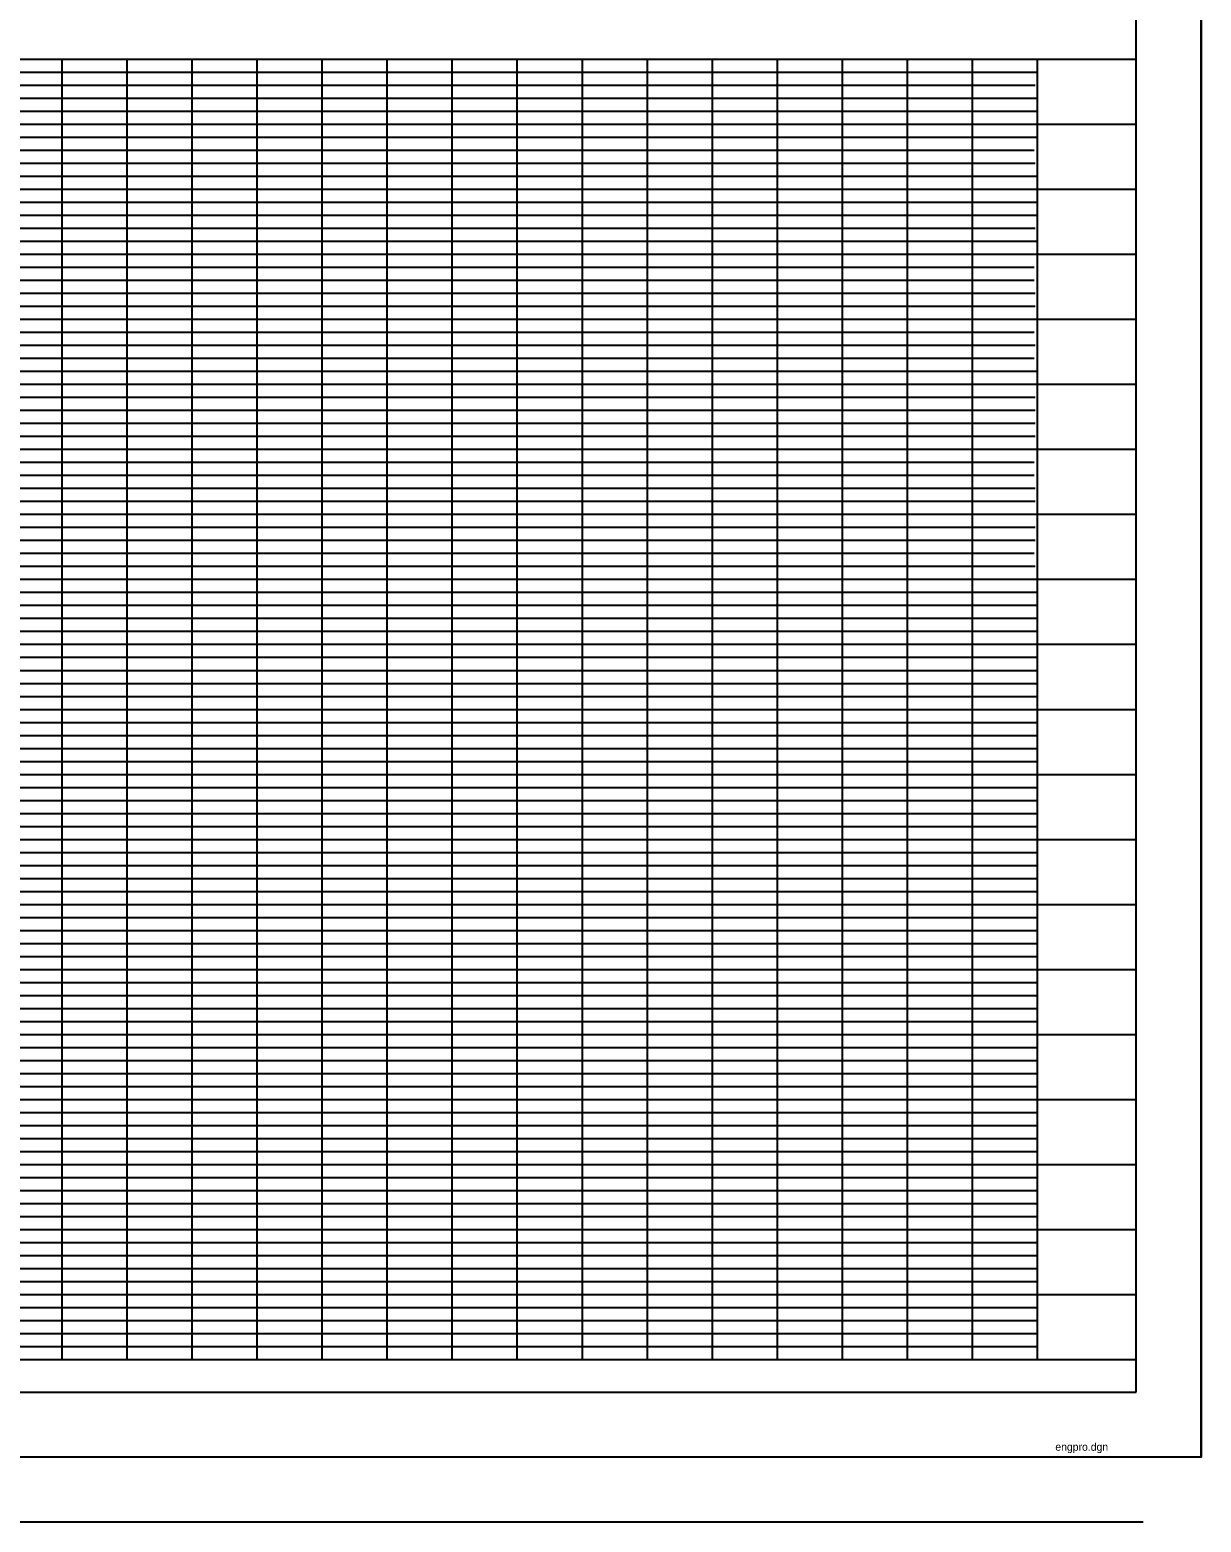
# Model space of a CAD drawing. Extents: x -184 to 1613, y -563 to 2888.
# Drawn here: x 1163 to 1613, y 588 to 1161 of the extents above; entities that cross this region are included whole.
import ezdxf

# ---------------------------------------------------------------- set-up
doc = ezdxf.new("R2010")
doc.units = 0
for name, color, linetype in [('RD_SHT_Bndy', 7, 'Continuous'), ('RD_SHT_IplotShp', 7, 'Continuous'), ('RD_SHT_MjGrid', 7, 'Continuous'), ('RD_SHT_MnGrid', 7, 'Continuous'), ('RD_SHT_Snap', 7, 'Continuous'), ('RD_SHT_SubGrid', 7, 'Continuous'), ('RD_SHT_TX', 7, 'Continuous')]:
    doc.layers.add(name, color=color, linetype=linetype)

msp = doc.modelspace()

# ---------------------------------------------------------------- linework, layer by layer
at = {"layer": 'RD_SHT_Bndy'}
for p, q in [((1588, 637.5), (1588, 1687.5)), ((-87, 1150), (1588, 1150)), ((1550, 1150), (1550, 650)), ((-87, 650), (1588, 650)), ((-87, 637.5), (1588, 637.5)), ((1590.65, 612.5), (-169.35, 612.5)), ((1590.65, 587.5), (-169.35, 587.5)), ((1590.65, 587.5), (-169.35, 587.5))]:
    msp.add_line(p, q, dxfattribs=at)
at = {"layer": 'RD_SHT_IplotShp'}
msp.add_lwpolyline([(-182.9, 1712.5), (1613, 1712.5), (1613, 612.5), (-182.9, 612.5)], close=True, dxfattribs=at)
at = {"layer": 'RD_SHT_MjGrid'}
for p, q in [((1200, 1150), (1200, 650)), ((1250, 1150), (1250, 650)), ((1300, 1150), (1300, 650)), ((1350, 1150), (1350, 650)), ((1400, 1150), (1400, 650)), ((1450, 1150), (1450, 650)), ((1500, 1150), (1500, 650)), ((-87, 1100), (1588, 1100)), ((-87, 1050), (1588, 1050)), ((-87, 1000), (1588, 1000)), ((-87, 950), (1588, 950)), ((-87, 900), (1588, 900)), ((-87, 850), (1588, 850)), ((-87, 800), (1588, 800)), ((-87, 750), (1588, 750)), ((-87, 700), (1588, 700))]:
    msp.add_line(p, q, dxfattribs=at)
at = {"layer": 'RD_SHT_MnGrid'}
for p, q in [((1175, 1150), (1175, 650)), ((1225, 1150), (1225, 650)), ((1275, 1150), (1275, 650)), ((1325, 1150), (1325, 650)), ((1375, 1150), (1375, 650)), ((1425, 1150), (1425, 650)), ((1475, 1150), (1475, 650)), ((1525, 1150), (1525, 650)), ((-87, 1125), (1588, 1125)), ((-87, 1075), (1588, 1075)), ((-87, 1025), (1588, 1025)), ((-87, 975), (1588, 975)), ((-87, 925), (1588, 925)), ((-87, 875), (1588, 875)), ((-87, 825), (1588, 825)), ((-87, 775), (1588, 775)), ((-87, 725), (1588, 725)), ((-87, 675), (1588, 675))]:
    msp.add_line(p, q, dxfattribs=at)
at = {"layer": 'RD_SHT_Snap'}
msp.add_line((1613, 612.5), (1613, 1712.5), dxfattribs=at)
at = {"layer": 'RD_SHT_SubGrid'}
for p, q in [((-49.95, 1145), (1549.8, 1145)), ((-49.95, 1140), (1549.25, 1140)), ((-49.95, 1135), (1549.8, 1135)), ((-49.9, 1130), (1549.8, 1130)), ((-49.95, 1120), (1549.8, 1120)), ((-49.95, 1115), (1548.75, 1115)), ((-49.95, 1110), (1549.25, 1110)), ((-49.95, 1105), (1549.8, 1105)), ((-49.95, 1095), (1549.8, 1095)), ((-49.95, 1090), (1549.8, 1090)), ((-49.95, 1085), (1549.25, 1085)), ((-49.95, 1080), (1549.8, 1080)), ((-49.95, 1070), (1548.75, 1070)), ((-49.95, 1065), (1548.75, 1065)), ((-49.95, 1060), (1549.25, 1060)), ((-49.95, 1055), (1549.25, 1055)), ((-49.95, 1045), (1548.75, 1045)), ((-49.95, 1040), (1549.25, 1040)), ((-49.95, 1035), (1548.75, 1035)), ((-49.9, 1030), (1549.8, 1030)), ((-49.95, 1020), (1549.25, 1020)), ((-49.95, 1015), (1549.25, 1015)), ((-49.95, 1010), (1549.25, 1010)), ((-49.95, 1005), (1549.25, 1005)), ((-49.85, 995), (1548.75, 995)), ((-49.85, 990), (1548.75, 990)), ((-49.9, 985), (1549.25, 985)), ((-49.9, 980), (1549.25, 980)), ((-49.95, 970), (1549.25, 970)), ((-49.95, 965), (1549.25, 965)), ((-49.95, 960), (1548.75, 960)), ((-49.95, 955), (1549.25, 955)), ((-49.95, 955), (1549.25, 955)), ((-49.95, 945), (1549.8, 945)), ((-49.95, 940), (1549.8, 940)), ((-49.95, 935), (1549.8, 935)), ((-49.95, 930), (1549.8, 930)), ((-49.95, 920), (1549.8, 920)), ((-49.95, 915), (1549.8, 915)), ((-49.95, 910), (1549.8, 910)), ((-49.95, 905), (1549.8, 905)), ((-49.95, 895), (1549.85, 895)), ((-49.95, 890), (1549.85, 890)), ((-49.95, 885), (1549.85, 885)), ((-49.95, 880), (1549.85, 880)), ((-49.95, 870), (1549.85, 870)), ((-49.95, 865), (1549.85, 865)), ((-49.95, 860), (1549.85, 860)), ((-49.95, 855), (1549.85, 855)), ((-49.95, 845), (1549.85, 845)), ((-49.95, 840), (1549.85, 840)), ((-49.95, 835), (1549.85, 835)), ((-49.95, 830), (1549.85, 830)), ((-49.95, 820), (1549.85, 820)), ((-49.95, 815), (1549.85, 815)), ((-49.9, 820), (1549.85, 820)), ((-49.9, 810), (1549.6, 810)), ((-49.9, 805), (1549.6, 805)), ((-49.9, 795), (1549.8, 795)), ((-49.95, 790), (1549.95, 790)), ((-49.95, 785), (1549.95, 785)), ((-49.9, 780), (1549.95, 780)), ((-49.95, 770), (1549.95, 770)), ((-49.95, 765), (1549.95, 765)), ((-49.95, 760), (1549.95, 760)), ((-49.9, 755), (1549.95, 755)), ((-49.95, 745), (1549.95, 745)), ((-49.95, 740), (1549.95, 740)), ((-49.95, 735), (1549.95, 735)), ((-49.95, 730), (1549.85, 730)), ((-49.9, 720), (1549.6, 720)), ((-49.95, 715), (1549.85, 715)), ((-49.95, 710), (1549.85, 710)), ((-49.95, 705), (1549.85, 705)), ((-49.85, 695), (1549.85, 695)), ((-49.95, 690), (1549.85, 690)), ((-49.95, 685), (1549.85, 685)), ((-49.95, 680), (1549.85, 680)), ((-49.85, 670), (1549.85, 670)), ((-49.85, 665), (1549.85, 665)), ((-49.85, 660), (1549.85, 660)), ((-49.85, 655), (1549.85, 655))]:
    msp.add_line(p, q, dxfattribs=at)

# ---------------------------------------------------------------- texts
at = {"layer": 'RD_SHT_TX'}
msp.add_text('engpro.dgn', height=3, dxfattribs=at).set_placement((1556.95, 614.95))

doc.saveas('drawing.dxf')
